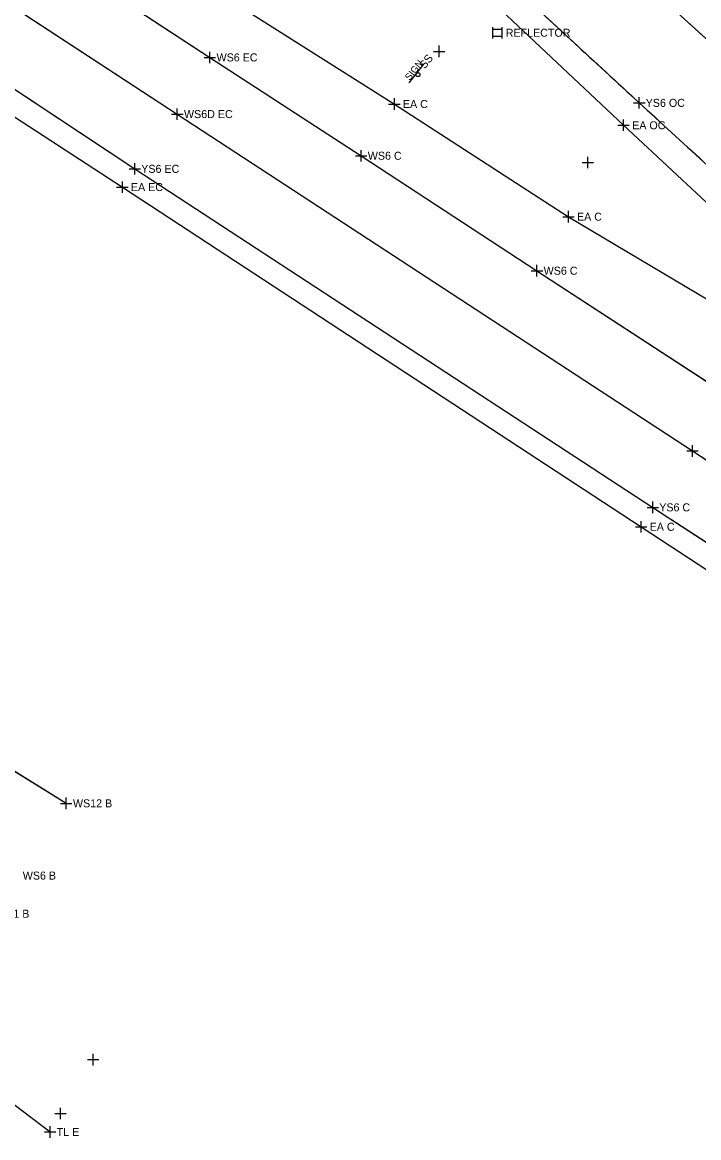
# Model space of a CAD drawing. Extents: x 1324236 to 1326110, y 459090 to 460782.
# Drawn here: x 1325790.8 to 1325909.2, y 459455.4 to 459650.5 of the extents above; entities that cross this region are included whole.
import ezdxf

# ---------------------------------------------------------------- set-up
doc = ezdxf.new("R2010")
doc.units = 0
for name, color, linetype in [('BD_X_Canopy', 7, 'Continuous'), ('DR_X_Ditch', 7, 'Continuous'), ('DT_X_Contour_Minor', 7, 'Continuous'), ('DT_X_Terrain_Ground_Line', 7, 'Continuous'), ('DV_X_Property_Line', 7, 'Continuous'), ('LT_X_Poles', 7, 'Continuous'), ('PM_X_Edge_Line', 7, 'Continuous'), ('PM_X_Lane_Line', 7, 'Continuous'), ('PV_X_Shoulder', 7, 'Continuous'), ('RD_X_GR_Lt', 7, 'Continuous'), ('RW_X_CL', 7, 'Continuous'), ('RW_X_Esmt_SH', 7, 'Continuous')]:
    doc.layers.add(name, color=color, linetype=linetype)

msp = doc.modelspace()

# ---------------------------------------------------------------- linework, layer by layer
at = {"layer": 'BD_X_Canopy'}
msp.add_lwpolyline([(1325729.36, 459692.27), (1325817.9, 459634.46), (1325908.1, 459575.52), (1325982.49, 459526.91), (1326043.74, 459486.99)], dxfattribs=at)
at = {"layer": 'DR_X_Ditch'}
for points in [[(1325722.82, 459682.9), (1325810.46, 459624.88), (1325901.15, 459565.66), (1325983.77, 459511.89), (1326013.21, 459492.94)], [(1325794.01, 459663.73), (1325823.6, 459644.37), (1325850.08, 459627.17), (1325880.87, 459607.06), (1325914.36, 459585.21)], [(1325894.93, 459661.79), (1325910.38, 459647.75), (1325910.38, 459647.75), (1325925.26, 459634.33), (1325925.26, 459634.33), (1325935.02, 459625.6), (1325935.02, 459625.6), (1325945.3, 459616.54), (1325945.3, 459616.54), (1325958.74, 459604.86), (1325958.74, 459604.86), (1325972.97, 459592.68), (1325972.97, 459592.68), (1325984.11, 459583.31), (1325984.11, 459583.31), (1325984.64, 459582.87), (1325984.64, 459582.87), (1326010.86, 459561.25), (1326010.86, 459561.25), (1326020.01, 459553.76), (1326020.01, 459553.76), (1326038.04, 459539.16), (1326038.04, 459539.16), (1326064, 459518.57)], [(1325929.76, 459608.19), (1325910.09, 459626.07), (1325910.09, 459626.07), (1325898.79, 459636.42), (1325898.79, 459636.42), (1325875.58, 459657.8)], [(1325798.46, 459513.88), (1325775.2, 459528.18), (1325745.11, 459546.59), (1325716.28, 459563.95), (1325685.92, 459582.25), (1325656.94, 459599.54), (1325627.71, 459616.8), (1325627.71, 459616.8), (1325598.12, 459633.73), (1325598.12, 459633.73)]]:
    msp.add_lwpolyline(points, dxfattribs=at)
at = {"layer": 'DT_X_Contour_Minor'}
msp.add_line((1325858.48, 459639.95), (1325861.06, 459643.18), dxfattribs=at)
msp.add_circle((1325860.04, 459641.35), 0.344, dxfattribs=at)
at = {"layer": 'DT_X_Terrain_Ground_Line'}
for p, q in [((1325873.1, 459649.69), (1325873.1, 459647.69)), ((1325873.1, 459649.29), (1325874.7, 459649.29)), ((1325874.7, 459649.69), (1325874.7, 459647.69)), ((1325873.1, 459648.09), (1325874.7, 459648.09))]:
    msp.add_line(p, q, dxfattribs=at)
at = {"layer": 'DV_X_Property_Line'}
for p, q in [((1325855.9, 459635.22), (1325855.9, 459637.22)), ((1325854.9, 459636.22), (1325856.9, 459636.22)), ((1325896.04, 459631.5), (1325896.04, 459633.5)), ((1325895.04, 459632.5), (1325897.04, 459632.5)), ((1325807.28, 459621.69), (1325809.28, 459621.69)), ((1325808.28, 459620.69), (1325808.28, 459622.69)), ((1325886.38, 459615.51), (1325886.38, 459617.51)), ((1325885.38, 459616.51), (1325887.38, 459616.51)), ((1325899.1, 459561.26), (1325899.1, 459563.26)), ((1325898.1, 459562.26), (1325900.1, 459562.26))]:
    msp.add_line(p, q, dxfattribs=at)
at = {"layer": 'LT_X_Poles'}
for points in [[(1325722.82, 459682.9), (1325810.46, 459624.88), (1325901.15, 459565.66), (1325983.77, 459511.89), (1326013.21, 459492.94)], [(1325794.01, 459663.73), (1325823.6, 459644.37), (1325850.08, 459627.17), (1325880.87, 459607.06), (1325914.36, 459585.21)], [(1325894.93, 459661.79), (1325910.38, 459647.75), (1325910.38, 459647.75), (1325925.26, 459634.33), (1325925.26, 459634.33), (1325935.02, 459625.6), (1325935.02, 459625.6), (1325945.3, 459616.54), (1325945.3, 459616.54), (1325958.74, 459604.86), (1325958.74, 459604.86), (1325972.97, 459592.68), (1325972.97, 459592.68), (1325984.11, 459583.31), (1325984.11, 459583.31), (1325984.64, 459582.87), (1325984.64, 459582.87), (1326010.86, 459561.25), (1326010.86, 459561.25), (1326020.01, 459553.76), (1326020.01, 459553.76), (1326038.04, 459539.16), (1326038.04, 459539.16), (1326064, 459518.57)], [(1325929.76, 459608.19), (1325910.09, 459626.07), (1325910.09, 459626.07), (1325898.79, 459636.42), (1325898.79, 459636.42), (1325875.58, 459657.8)]]:
    msp.add_lwpolyline(points, dxfattribs=at)
at = {"layer": 'PM_X_Edge_Line'}
for p, q in [((1325722.82, 459682.9), (1325810.46, 459624.88)), ((1325794.01, 459663.73), (1325823.6, 459644.37)), ((1325823.6, 459644.37), (1325850.08, 459627.17)), ((1325850.08, 459627.17), (1325880.87, 459607.06)), ((1325810.46, 459624.88), (1325901.15, 459565.66)), ((1325880.87, 459607.06), (1325914.36, 459585.21)), ((1325901.15, 459565.66), (1325983.77, 459511.89)), ((1325798.46, 459513.88), (1325775.2, 459528.18))]:
    msp.add_line(p, q, dxfattribs=at)
for centre, radius, start, end in [((1328987.09, 463048.48), 4585.97, 227.60289, 227.86372), ((1567038.49, 721510.71), 355986.65, 227.3553572, 227.3604353), ((1327992.78, 461910.48), 3091.3, 227.36044, 227.64449)]:
    msp.add_arc(centre, radius, start, end, dxfattribs=at)
at = {"layer": 'PM_X_Lane_Line'}
for p, q in [((1325729.36, 459692.27), (1325817.9, 459634.46)), ((1325817.9, 459634.46), (1325908.1, 459575.52)), ((1325908.1, 459575.52), (1325982.49, 459526.91))]:
    msp.add_line(p, q, dxfattribs=at)
at = {"layer": 'PV_X_Shoulder'}
for points in [[(1325721.22, 459678.38), (1325808.28, 459621.69), (1325899.1, 459562.26), (1325981.83, 459508.16), (1326020.97, 459482.83)], [(1325926.62, 459604.09), (1325907.09, 459622.18), (1325907.09, 459622.18), (1325896.04, 459632.5), (1325896.04, 459632.5), (1325872.66, 459654.48)], [(1325828.8, 459653.34), (1325855.9, 459636.22), (1325886.38, 459616.51), (1325921.35, 459595.71), (1325926.62, 459604.09)]]:
    msp.add_lwpolyline(points, dxfattribs=at)
at = {"layer": 'RD_X_GR_Lt'}
msp.add_line((1325770.28, 459475.65), (1325795.66, 459456.39), dxfattribs=at)
at = {"layer": 'RW_X_CL'}
for p, q in [((1325863.74, 459644.43), (1325863.74, 459646.43)), ((1325822.6, 459644.37), (1325824.6, 459644.37)), ((1325823.6, 459643.37), (1325823.6, 459645.37)), ((1325862.74, 459645.43), (1325864.74, 459645.43)), ((1325898.79, 459635.42), (1325898.79, 459637.42)), ((1325817.9, 459633.46), (1325817.9, 459635.46)), ((1325897.79, 459636.42), (1325899.79, 459636.42)), ((1325816.9, 459634.46), (1325818.9, 459634.46)), ((1325849.08, 459627.17), (1325851.08, 459627.17)), ((1325850.08, 459626.17), (1325850.08, 459628.17)), ((1325889.78, 459624.97), (1325889.78, 459626.97)), ((1325809.46, 459624.88), (1325811.46, 459624.88)), ((1325810.46, 459623.88), (1325810.46, 459625.88)), ((1325888.78, 459625.97), (1325890.78, 459625.97)), ((1325880.87, 459606.06), (1325880.87, 459608.06)), ((1325879.87, 459607.06), (1325881.87, 459607.06)), ((1325908.1, 459574.52), (1325908.1, 459576.52)), ((1325907.1, 459575.52), (1325909.1, 459575.52)), ((1325901.15, 459564.66), (1325901.15, 459566.66)), ((1325900.15, 459565.66), (1325902.15, 459565.66)), ((1325797.46, 459513.88), (1325799.46, 459513.88)), ((1325798.46, 459512.88), (1325798.46, 459514.88)), ((1325802.16, 459469.04), (1325804.16, 459469.04)), ((1325803.16, 459468.04), (1325803.16, 459470.04)), ((1325796.46, 459459.6), (1325798.46, 459459.6)), ((1325797.46, 459458.6), (1325797.46, 459460.6))]:
    msp.add_line(p, q, dxfattribs=at)
at = {"layer": 'RW_X_Esmt_SH'}
for p, q in [((1325795.66, 459455.39), (1325795.66, 459457.39)), ((1325794.66, 459456.39), (1325796.66, 459456.39))]:
    msp.add_line(p, q, dxfattribs=at)

# ---------------------------------------------------------------- texts
at = {"layer": 'DT_X_Contour_Minor'}
for s, height, p in [('SS', 1.4, (1325861.22, 459642.26)), ('SIGN', 1.205, (1325858.57, 459640.23))]:
    msp.add_text(s, height=height, rotation=51.3727, dxfattribs=at).set_placement(p)
at = {"layer": 'DV_X_Property_Line'}
for s, p in [('EA C', (1325857.4, 459635.52)), ('EA OC', (1325897.54, 459631.8)), ('EA EC', (1325809.78, 459620.99)), ('EA C', (1325887.88, 459615.81)), ('EA C', (1325900.6, 459561.56)), ('EA1 B', (1325786.7, 459493.87))]:
    msp.add_text(s, height=1.4, dxfattribs=at).set_placement(p)
at = {"layer": 'RW_X_CL'}
for s, p in [('WS6 EC', (1325824.77, 459643.67)), ('YS6 OC', (1325899.91, 459635.72)), ('WS6D EC', (1325819.07, 459633.76)), ('WS6 C', (1325851.25, 459626.47)), ('YS6 EC', (1325811.59, 459624.18)), ('WS6 C', (1325882.04, 459606.36)), ('YS6 C', (1325902.28, 459564.96)), ('WS12 B', (1325799.63, 459513.18)), ('WS6 B', (1325790.84, 459500.54))]:
    msp.add_text(s, height=1.4, dxfattribs=at).set_placement(p)
at = {"layer": 'RW_X_Esmt_SH'}
for s, p in [('REFLECTOR', (1325875.4, 459647.99)), ('TL E', (1325796.78, 459455.69))]:
    msp.add_text(s, height=1.4, dxfattribs=at).set_placement(p)

doc.saveas('drawing.dxf')
